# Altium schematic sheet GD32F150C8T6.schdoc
size 127 x 101 mm
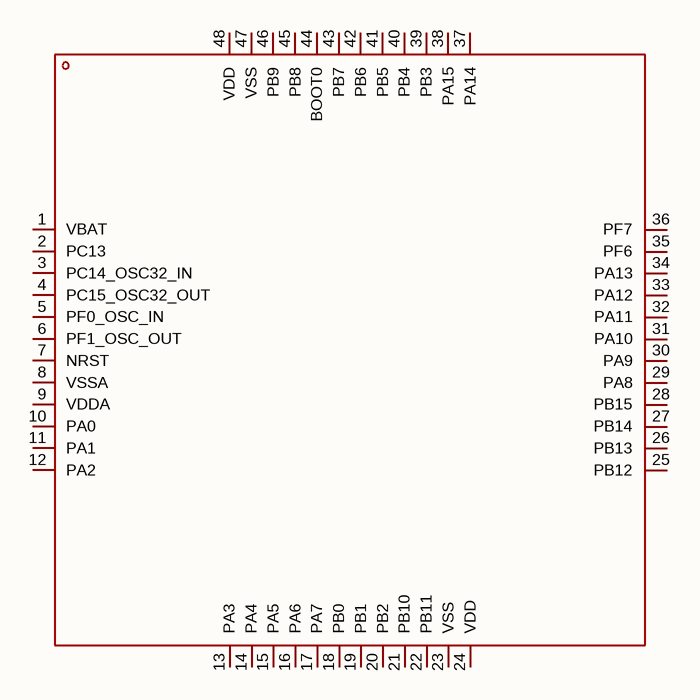
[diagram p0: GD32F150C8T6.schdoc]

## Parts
U?  gd32f150c8t6  [LQFP-48_L7.0-W7.0-P0.50-LS9.0-BL]  (value not drawn)

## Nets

Not connected (* = marked no-connect by the designer): U? 1(VBAT) 2(PC13) 3(PC14_OSC32_IN) 4(PC15_OSC32_OUT) 5(PF0_OSC_IN) 6(PF1_OSC_OUT) 7(NRST) 8(VSSA) 9(VDDA) 10(PA0) 11(PA1) 12(PA2) 13(PA3) 14(PA4) 15(PA5) 16(PA6) 17(PA7) 18(PB0) 19(PB1) 20(PB2) 21(PB10) 22(PB11) 23(VSS) 24(VDD) 25(PB12) 26(PB13) 27(PB14) 28(PB15) 29(PA8) 30(PA9) 31(PA10) 32(PA11) 33(PA12) 34(PA13) 35(PF6) 36(PF7) 37(PA14) 38(PA15) 39(PB3) 40(PB4) 41(PB5) 42(PB6) 43(PB7) 44(BOOT0) 45(PB8) 46(PB9) 47(VSS) 48(VDD)

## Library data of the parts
U? = gd32f150c8t6: CPU内核:ARM Cortex-M3;CPU最大主频:72MHz;CPU位数:32 Bit;; Manufacturer: GigaDevice(兆易创新); AddInBom: yes; ModelId: 093be70396ff421eb2cdb946d5311efc; ModelName: LQFP-48_L7.0-W7.0-H1.4-LS9.0-P0.50; ModelTransform: 354.331,354.331,0,0,0,0,0,0,0; CPU Maximum Speed: 72MHz; Core Size: 32 Bit; Program Storage Size: 64KB; Program Memory Type: FLASH; Number of I/O: 39; ADC (Bit): 12bit; Voltage - Supply: 2.6V~3.6V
